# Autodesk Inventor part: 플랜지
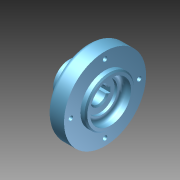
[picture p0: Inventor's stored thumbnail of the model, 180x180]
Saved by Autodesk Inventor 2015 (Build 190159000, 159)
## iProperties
Created: 2026-04
Part Number: 플랜지
Material: 일반
Document SubType Name: Modeling
Designer: User
Density: 1 g/cm^3
Appearance: 기본값
Author: User
Author: jhkim
Creation Date: 2026-03-26
Sending System: Autodesk Inventor 2026
Preprocessor: ST-DEVELOPER v20.1
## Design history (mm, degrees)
node "플랜지1"
node "솔리드1"
node "기준1"
